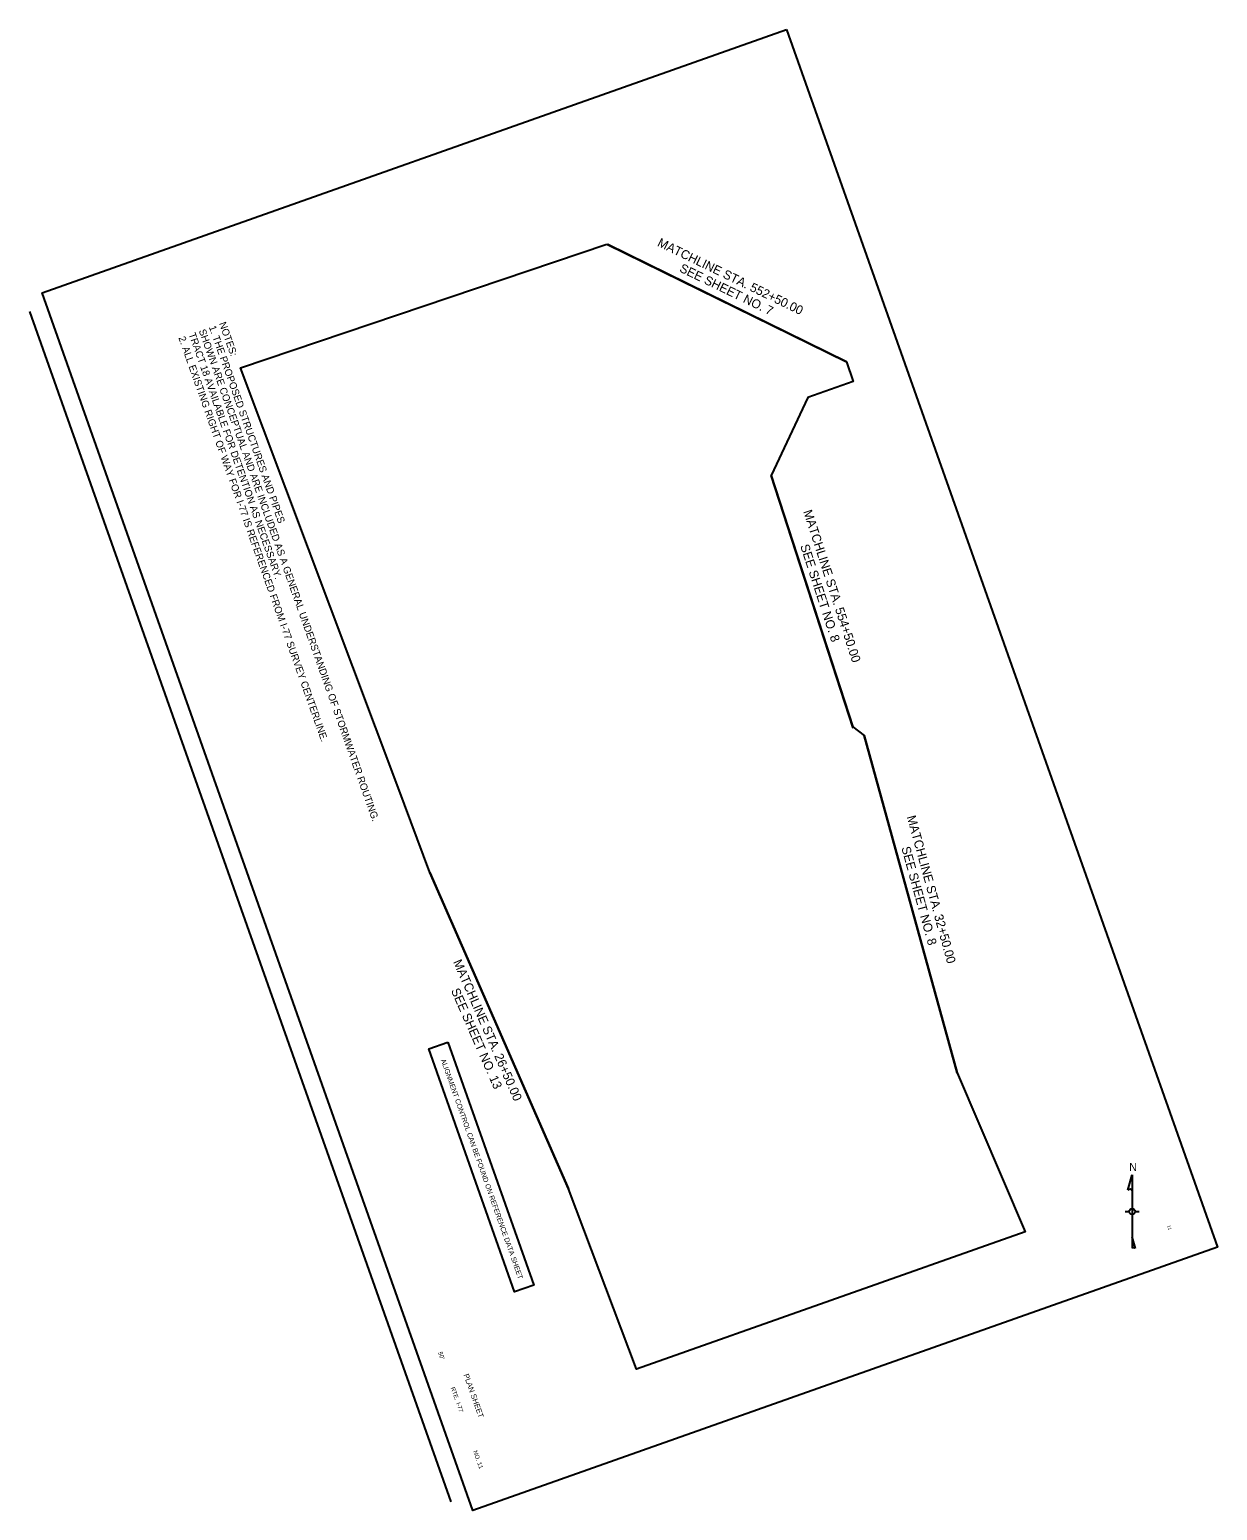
# Model space of a CAD drawing. Extents: x 2004383 to 2006037, y 1136152 to 1138216.
import ezdxf

# ---------------------------------------------------------------- set-up
doc = ezdxf.new("R2010")
doc.units = 0
for name, color, linetype in [('North Arrow', 7, 'Continuous'), ('RD_SHT_IplotShp', 7, 'Continuous'), ('RD_SHT_MatchLine', 7, 'Continuous'), ('RD_SHT_Misc1', 7, 'Continuous'), ('RD_SHT_ShtClip', 7, 'Continuous'), ('RD_SHT_TX', 7, 'Continuous')]:
    doc.layers.add(name, color=color, linetype=linetype)

msp = doc.modelspace()

# ---------------------------------------------------------------- linework, layer by layer
at = {"layer": 'North Arrow'}
for p, q in [((2005912.8, 1136598.4), (2005918.8, 1136619.4)), ((2005918.8, 1136619.4), (2005918.8, 1136597.2)), ((2005918.8, 1136619.4), (2005918.8, 1136517.2)), ((2005909, 1136568.3), (2005914.7, 1136568.3)), ((2005922.8, 1136568.3), (2005928.5, 1136568.3)), ((2005918.8, 1136533), (2005918.8, 1136517.2)), ((2005923.3, 1136516.9), (2005918.8, 1136533))]:
    msp.add_line(p, q, dxfattribs=at)
msp.add_circle((2005918.8, 1136568.3), 4.02, dxfattribs=at)
for centre, radius, start, end in [((2005915.4, 1136595.9), 3.59, 22.3707, 136.1387), ((2005920.9, 1136514.7), 3.3, 43.3397, 130.5607)]:
    msp.add_arc(centre, radius, start, end, dxfattribs=at)
at = {"layer": 'RD_SHT_IplotShp'}
msp.add_lwpolyline([(2005437.1, 1138215.7), (2006037.5, 1136518.7), (2005000.4, 1136151.9), (2004400.1, 1137848.8)], close=True, dxfattribs=at)
at = {"layer": 'RD_SHT_MatchLine'}
for p, q in [((2005520.6, 1137752.8), (2005188.2, 1137916)), ((2005530, 1137242), (2005415.7, 1137594.3)), ((2005675, 1136761.7), (2005545.6, 1137231.7)), ((2004940.5, 1137040.7), (2005133.6, 1136600.2))]:
    msp.add_line(p, q, dxfattribs=at)
at = {"layer": 'RD_SHT_ShtClip'}
msp.add_lwpolyline([(2005187.1, 1137916.5), (2005520.6, 1137752.8), (2005530.3, 1137725.3), (2005466.7, 1137702.8), (2005415.7, 1137594.3), (2005529.5, 1137243.8), (2005545.6, 1137231.7), (2005675, 1136761.7), (2005769.8, 1136540.1), (2005228.3, 1136348.6), (2005133.6, 1136600.2), (2004940.5, 1137040.7), (2004896, 1137159.3), (2004676.4, 1137744.4)], close=True, dxfattribs=at)
at = {"layer": 'RD_SHT_TX'}
msp.add_line((2004382.8, 1137822.9), (2004969.7, 1136163.7), dxfattribs=at)
msp.add_line((2004382.8, 1137822.9), (2004969.7, 1136163.7), dxfattribs=at)
msp.add_lwpolyline([(2004965.4, 1136804.4), (2005085.2, 1136465.8), (2005058.4, 1136456.4), (2004938.7, 1136795)], close=True, dxfattribs=at)

# ---------------------------------------------------------------- texts
at = {"layer": 'North Arrow'}
msp.add_text('N', height=11.1, dxfattribs=at).set_placement((2005914.7, 1136624.9))
at = {"layer": 'RD_SHT_MatchLine'}
for s, rotation, p in [('MATCHLINE STA. 552+50.00', 334.1631, (2005256.3, 1137914.6)), ('SEE SHEET NO. 7', 334.1631, (2005287, 1137878.9)), ('MATCHLINE STA. 554+50.00', 287.9765, (2005460.4, 1137544.1)), ('SEE SHEET NO. 8', 287.9765, (2005456.2, 1137496.2)), ('MATCHLINE STA. 32+50.00', 285.3889, (2005604.7, 1137118.6)), ('SEE SHEET NO. 8', 285.3889, (2005597.1, 1137075.4)), ('MATCHLINE STA. 26+50.00', 293.5949, (2004972.5, 1136916.4)), ('SEE SHEET NO. 13', 293.5949, (2004969.5, 1136876.5))]:
    msp.add_text(s, height=12.5, rotation=rotation, dxfattribs=at).set_placement(p)
at = {"layer": 'RD_SHT_Misc1'}
for s, p in [('SHOWN ARE CONCEPTUAL AND ARE INCLUDED AS A GENERAL UNDERSTANDING OF STORMWATER ROUTING.  ', (2004618.2, 1137796.2)), ('1. THE PROPOSED STRUCTURES AND PIPES ', (2004632.3, 1137801.2)), ('NOTES:', (2004646.5, 1137806.2)), ('2. ALL EXISTING RIGHT OF WAY FOR I-77 IS REFERENCED FROM I-77 SURVEY CENTERLINE.', (2004589.9, 1137786.2)), ('TRACT 18 AVAILABLE FOR DETENTION AS NECESSARY. ', (2004604.1, 1137791.2))]:
    msp.add_text(s, height=10, rotation=289.482, dxfattribs=at).set_placement(p)
at = {"layer": 'RD_SHT_TX'}
for s, height, p in [('ALIGNMENT CONTROL CAN BE FOUND ON REFERENCE DATA SHEET', 7, (2004955.4, 1136779.8)), ('11', 4.5, (2005967.5, 1136548.6)), ("50'", 6, (2004951.8, 1136371.8)), ('PLAN SHEET', 7.5, (2004987.1, 1136340.8)), ('RTE.', 6, (2004969.2, 1136322.7)), ('I-77', 6, (2004976.8, 1136301.2)), ('NO.', 6, (2005000.5, 1136234.2)), ('11', 6, (2005006.3, 1136217.9))]:
    msp.add_text(s, height=height, rotation=289.482, dxfattribs=at).set_placement(p)

doc.saveas('drawing.dxf')
